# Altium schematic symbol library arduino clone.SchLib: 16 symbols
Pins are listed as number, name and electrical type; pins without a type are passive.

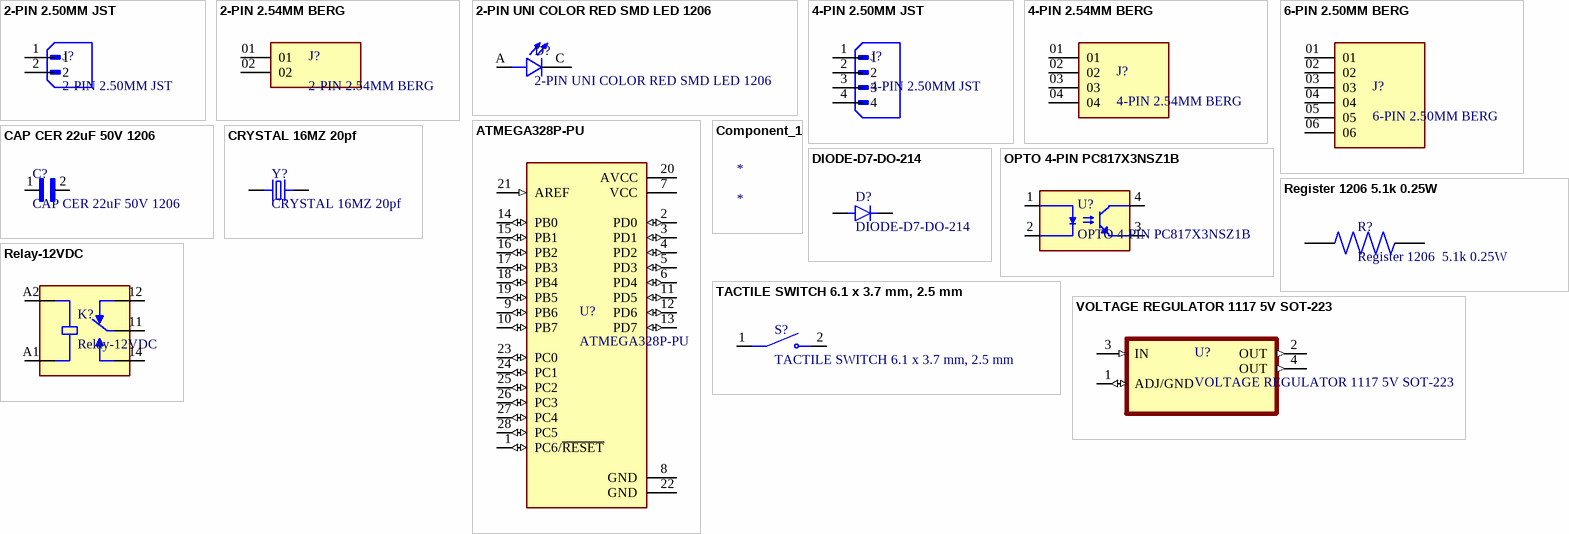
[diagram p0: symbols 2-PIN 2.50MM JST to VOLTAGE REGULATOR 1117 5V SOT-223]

## 2-PIN 2.50MM JST
designator J?
Connector Header Through Hole 2 position 0.098 (2.50mm); MF: JST Sales; MP: B2B-XH-A(LF)(SN)
footprint 2-PIN 2.50MM JST
pins: 1, 2

## 2-PIN 2.54MM BERG
designator J?
2 pin berg connector 2.54mm MTLW-102-08-L-S-300
footprint 2-PIN 2.54MM BERG (SAMTEC_MTLW-102-08-L-S-300)
pins: 01, 02

## 2-PIN UNI COLOR RED SMD LED 1206
designator D?
LED Uni-Color Red 660nm 2-Pin SMD T/R; MP: BR1102W-TR
footprint 2-PIN UNI COLOR RED SMD LED 1206 (LED_BR1102W-TR)
pins: A, C

## 4-PIN 2.50MM JST
designator J?
Connector Header Through Hole 4 position 0.098 (2.50mm); MF: JST Sales; MP: B4B-XH-A
footprint 4-PIN 2.54MM JST (JST_B4B-XH-A)
pins: 1, 2, 3, 4

## 4-PIN 2.54MM BERG
designator J?
4 pin berg connector 2.54mm MTSW-104-22-S-S-415
footprint 4-PIN 2.54MM BERG (SAMTEC_MTSW-104-22-S-S-415)
pins: 01, 02, 03, 04

## 6-PIN 2.50MM BERG
designator J?
berg-connector-6pos-2.54mm; MF: Samtec; MP: SSQ-106-02-G-S-LL
footprint 6-PIN 2.54MM BERG (berg-connector-6pin-2.54mm)
pins: 01, 02, 03, 04, 05, 06

## ATMEGA328P-PU
designator U?
ATmega Series 20 MHz 32 KB Flash 2 KB SRAM 8-Bit Microcontroller - DIP-28
footprint Atmega328pU DIP Controller (Atmega328pU DIP)
pins: 1 PC6/~{RESET} (io), 2 PD0 (io), 3 PD1 (io), 4 PD2 (io), 5 PD3 (io), 6 PD4 (io), 7 VCC (power), 8 GND (power), 9 PB6 (io), 10 PB7 (io), 11 PD5 (io), 12 PD6 (io), 13 PD7 (io), 14 PB0 (io), 15 PB1 (io), 16 PB2 (io), 17 PB3 (io), 18 PB4 (io), 19 PB5 (io), 20 AVCC (power), 21 AREF (in), 22 GND (power), 23 PC0 (io), 24 PC1 (io), 25 PC2 (io), 26 PC3 (io), 27 PC4 (io), 28 PC5 (io)

## CAP CER 22uF 50V 1206
designator C?
C1206C101J2GACTU CAP CER 100PF 200V C0G/NP0 1206
footprint capacitor 100nF 1206
pins: 1, 2

## Component_1
designator *

## CRYSTAL 16MZ 20pf
designator Y?
16 MHz Â±30ppm Crystal 20pF 40 Ohms HC-49/US ECS-160-20-5PX-TR; MF: ECS Inc.
footprint CRYSTAL 16MZ 20pf (XTAL_ECS-160-20-5PX-TR)
pins: 1, 2

## DIODE-D7-DO-214
designator D?
MF: Diodes Inc.; MP: S1M-13-F
footprint diode-d7-DO-214
pins: A, C

## OPTO 4-PIN PC817X3NSZ1B
designator U?
Optoisolator Transistor Output - 1 Channel 4-DIP; MF: Sharp Microelectronics
footprint OPTO 4-PIN PC817X3NSZ1B (DIP762W50P254L495H455Q4)
pins: 1 ANODE, 2 CATHODE, 3 EMITTER, 4 COLLECTOR

## Register 1206 5.1k 0.25W
designator R?, comment Register 1206  5.1k 0.25W
Register 1206 10kohm; MP: RNCF1206BKY10K0
footprint Register 1206 10kohm (Register RESC3015X65N)
pins: 1, 2

## Relay-12VDC
designator K?
833H Series 10 A SPDT 12 VDC Through Hole Miniature Sugar Cube Power Relay 833H-1C-S-; MF: Song Chuan; MP: 833H-1C-S-12VDC
footprint Relay-12VDC (RELAY_833H-1C-S-12VDC)
pins: 11 COM, 12 NC, 14 NO, A1 COIL2, A2 COIL1

## TACTILE SWITCH 6.1 x 3.7 mm, 2.5 mm
designator S?
6.1 x 3.7 mm, 2.5 mm Actuator Height, 260 gf, Red, Surface Mount, SPST, Tactile Switch TS09-63-25-R-260-SMT-TR; MF: Same Sky
footprint TACTILE SWITCH 6.1 x 3.7 mm, 2.5 mm (PUSHBUTTON_SMD_6.1 x 3.7 mm, 2.5 mm)
pins: 1, 2

## VOLTAGE REGULATOR 1117 5V SOT-223
designator U?
800-mA, 15-V, linear voltage regulator 4-SOT-223 0 to 125 TLV1117-50CDCYRG3; MF: Texas Instruments
footprint VOLTAGE REGULATOR 1117 5V SOT-223 (SOT230P700X180-4N)
pins: 1 ADJ/GND (io), 2 OUT (out), 3 IN (in), 4 OUT (out)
